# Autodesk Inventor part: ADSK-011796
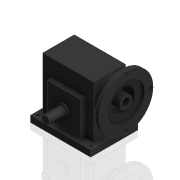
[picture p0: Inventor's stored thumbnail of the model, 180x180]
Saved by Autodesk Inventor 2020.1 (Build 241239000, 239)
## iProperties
Created: 2000-02
Part Number: ADSK-011796
Material: Pearson HRS
Document SubType Name: Modeling
Designer: mpflueger
Density: 7.83 g/cm^3
Appearance: Rubber-Black
Mass: 27856.1 g
Surface Area: 2387.07 cm^2
Volume: 3557.61 cm^3
Control State: 0
Master: False
Checked Out: False
Shininess: 0.0
Length Units: 11269
Angle Units: 11279
Time Units: 11290
Mass Units: 11283
Length Display Precision: 3
Angle Display Precision: 2
Compacted: True
Dimensions: 220x209,5x236 mm
Mass: 27,856 kg
VLT_Material: Pearson HRS
DocNumber: ADSK-011796.ipt
Folder: 01 - Themengebiete\Simplification\01 - Packaging machine\
VDS_Category: 3D Komponenten
Density: 0.0
Volumn: 0.0
Area: 0.0
PropertySet Name: Model Information
Author: mpflueger
Revision Number: -
Title: gearbox
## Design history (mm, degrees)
node "Extrusion1" dims "d2" = 19, "d3" = 0
  sketch "Sketch1"
    geometry: L1 (-72, -92)-(72, -92); L2 (72, -92)-(72, 92); L3 (72, 92)-(-72, 92); L4 (-72, 92)-(-72, -92); L5 (0, 92)-(0, -92); L6 (-72, 0)-(72, 0); 1 further point
    constraints: 12 end point, 6 midpoint, 2 parallel, 1 horizontal, 1 perpendicular
    dimensions: "d0" = 72 distance between parallel lines of L4 L5; "d1" = 92 distance between parallel lines of L3 L6
node "Hole1" dims "d8" = 9, "d9" = 9.525, "d10" = 6.35, "d11" = 60 deg, "d12" = 19.05, "d13" = 118 deg, "d68" = 6
  sketch "Sketch2"
    geometry: L1 (60, 81)-(-60, 81); L2 (-60, 81)-(-60, -81); L3 (-60, -81)-(60, -81); L4 (60, -81)-(60, 81); 5 further points
    constraints: 8 end point, 3 horizontal alignment, 3 vertical alignment, 2 midpoint, 2 parallel, 1 horizontal, 1 perpendicular
    dimensions: "d66" = 162 distance of L3.end L1.start; "d67" = 120 distance of L1.start L1.end
node "Extrusion2" dims "d16" = 160, "d17" = 0
  sketch "Sketch3" dims "d61" = 5
    geometry: L1 (-48, -78)-(48, -78); L2 (48, -78)-(48, 78); L3 (48, 78)-(-48, 78); L4 (-48, 78)-(-48, -78); L5 (0, 78)-(0, -78); L6 (-48, 0)-(48, 0); 1 further point
    constraints: 12 end point, 6 midpoint, 2 parallel, 1 horizontal, 1 perpendicular
    dimensions: "d14" = 48 distance between parallel lines of L4 L5; "d15" = 78 distance between parallel lines of L3 L6
node "Extrusion3" dims "d21" = 14, "d22" = 0
  sketch "Sketch4"
    geometry: L1 (0, 0)-(0, 156) reference; L2 (-160, 0)-(-160, 156) reference; L3 (-52, 129)-(-154, 129); L4 (-154, 129)-(-154, 27); L5 (-154, 27)-(-52, 27); L6 (-52, 27)-(-52, 129); L7 (-52, 78)-(-154, 78); L8 (-103, 27)-(-103, 129); L9 (0, 78)-(-160, 78); L10 (-160, -14)-(-160, 170) reference
    constraints: 14 end point, 6 midpoint, 2 parallel, 1 collinear, 1 horizontal, 1 perpendicular
    dimensions: "d18" = 57 distance between parallel lines of L8 L10; "d19" = 102 distance of L3.start L3.end; "d20" = 102 distance of L3.end L4.end (= d19)
node "Extrusion4" dims "d24" = 6, "d25" = 0
  sketch "Sketch5"
    geometry: L1 (-52, 129)-(-52, 27) reference; L2 (-154, 129)-(-52, 129) reference; L3 (-154, 27)-(-154, 129) reference; L4 (-52, 27)-(-154, 27) reference; L5 (-103, 129)-(-103, 27); L6 (-154, 78)-(-52, 78); C1 r 16 at (-103, 78)
    constraints: 5 midpoint, 4 end point, 1 centre point
    dimensions: "d23" = 32 diameter of C1
node "Extrusion5" dims "d27" = 50, "d28" = 0
workplane "Work Plane1"
node "Extrusion6" dims "d32" = 6, "d33" = 0
  sketch "Sketch7"
    geometry: L1 (68, -12.694)-(118, -12.694) reference; L2 (68, 12.694)-(118, 12.694) reference; L3 (118, 12.694)-(118, -12.694) reference; L4 (118, -3)-(88, -3); L5 (88, 3)-(118, 3); L6 (118, 3)-(118, -3); L7 (118, 0)-(80.948, 0); L8 (118, 0)-(76.71, 0); A1 r 3 centre (88, 0) between (88, 3) and (88, -3)
    constraints: 10 end point, 3 collinear, 2 midpoint, 2 point on circle, 2 tangent, 1 centre point, 1 horizontal, 1 parallel, 1 perpendicular
    dimensions: "d30" = 6 distance of L5.end L4.start; "d31" = 30 distance from line of A1.centre L6
chamfer "Fase1" distance "d70" = 1; stored, may be unused: second distance "d71" = 2, angle "d72" = 45 deg
node "Mirror1"
node "Extrusion7" dims "d37" = 4, "d38" = 0
  sketch "Sketch8"
    geometry: L1 (0, 0)-(96, 0) reference; L2 (0, 160)-(96, 160) reference; L3 (48, 0)-(48, 160); L4 (-24, 179)-(120, 179) reference; C1 r 36.576 at (48, 52)
    constraints: 2 end point, 2 midpoint, 1 centre point, 1 point on line
    dimensions: "d35" = 127 distance from line of C1.centre L4; "d36" = 73.152 diameter of C1
node "Extrusion8" dims "d39" = 38, "d40" = 0
  sketch "Sketch9"
    geometry: L1 (96, -160)-(96, 0) reference; C1 r 36.576 at (48, -52) reference; C2 r 48 at (48, -52)
    constraints: 1 centre point, 1 coincident, 1 tangent
node "Extrusion9" dims "d42" = 12, "d43" = 0
  sketch "Sketch10"
    geometry: C1 r 36.576 at (0, 0) reference; C2 r 48 at (0, 0) reference; C3 r 82.5 at (0, 0); C4 r 36.554 at (0, 0)
    constraints: 2 centre point, 2 coincident, 1 concentric
    dimensions: "d41" = 165 diameter of C3
node "Hole2" dims "d45" = 9, "d46" = 9.525, "d47" = 6.35, "d48" = 60 deg, "d49" = 19.05, "d50" = 118 deg, "d73" = 6
  sketch "Sketch11"
    geometry: C1 r 36.576 at (0, 0) reference; A1 r 74 centre (0, 0) between (74, 0) and (0, 74); 2 further points
    constraints: 4 point on circle, 2 horizontal alignment, 2 vertical alignment, 1 centre point, 1 coincident
    dimensions: "d44" = 148 diameter of A1
node "Extrusion10" dims "d53" = 10, "d54" = 0
  sketch "Sketch12"
    geometry: C1 r 36.576 at (0, 0) reference; C2 r 82.5 at (0, 0) reference; C3 r 57 at (0, 0)
    constraints: 1 centre point, 1 coincident
    dimensions: "d51" = 114 diameter of C3
node "Extrusion11" dims "d56" = 50, "d57" = 0
  sketch "Sketch13"
    geometry: C1 r 36.576 at (0, 0) reference; C2 r 19 at (0, 0)
    constraints: 1 centre point, 1 coincident
    dimensions: "d55" = 38 diameter of C2
node "Extrusion12" dims "d59" = 50, "d60" = 0
  sketch "Sketch14"
    geometry: C1 r 19 at (0, 0) reference; C2 r 11 at (0, 0)
    constraints: 1 centre point, 1 coincident
    dimensions: "d58" = 22 diameter of C2
node "Extrusion13" dims "d64" = 38, "d65" = 0
  sketch "Sketch15"
    geometry: L1 (-2.5, 8.5)-(2.5, 8.5); L2 (2.5, 8.5)-(2.5, 13.5); L3 (2.5, 13.5)-(-2.5, 13.5); L4 (-2.5, 13.5)-(-2.5, 8.5); L5 (0, 13.5)-(0, 0); L6 (0, 0)-(-3.918, 0); C1 r 19 at (0, 0) reference
    constraints: 12 end point, 2 parallel, 2 perpendicular, 1 horizontal, 1 midpoint, 1 vertical
    dimensions: "d61" = 5 distance of L2.end L3.end; "d62" = 13.5 distance between parallel lines of L3 L6 (= 0.5 x d58 + 0.5 x d61); "d63" = 5 distance of L3.end L1.start (= d61)
fillet "Rundung2"
node "Solide1"
node "Corps solides"
node "Corps surfaciques"
sketch "Sketch6"
  geometry: C1 r 16 at (0, 0) reference; C2 r 12.694 at (0, 0)
  constraints: 1 centre point, 1 coincident
  dimensions: "d26" = 25.3873 diameter of C2
other parameters: "d29" = -91.81465
